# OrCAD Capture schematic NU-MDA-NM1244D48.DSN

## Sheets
1 Connect: size A4; title: Nu-MDA-NM1244D48_Connect; rev: V1.0
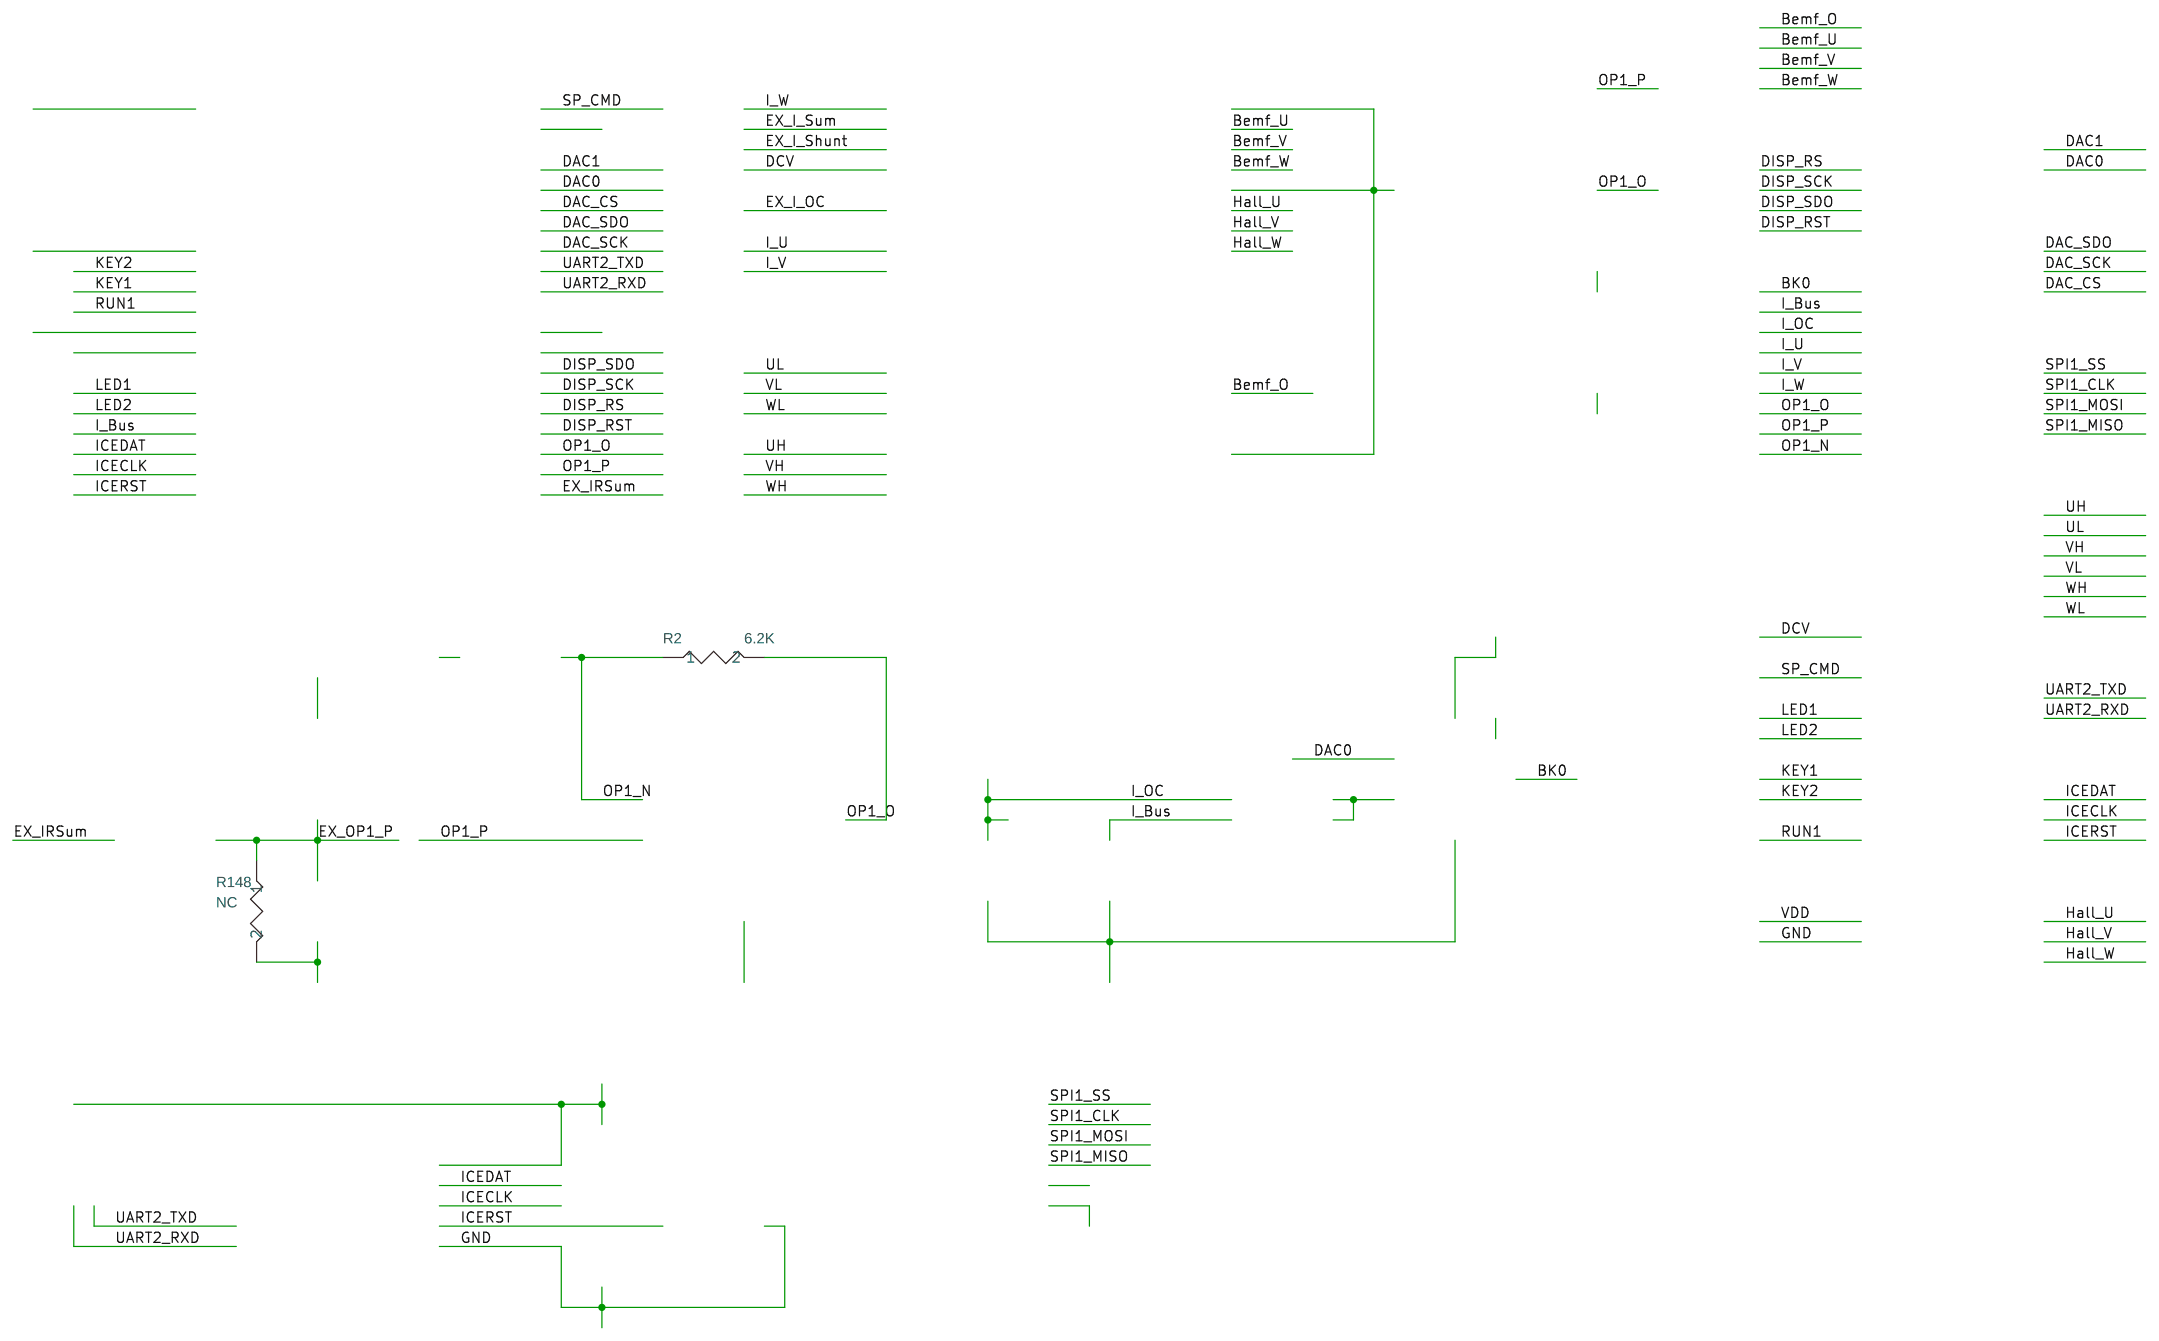
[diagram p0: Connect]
2 NM1244D48: size A3; title: Nu-MDA-NM1244D48
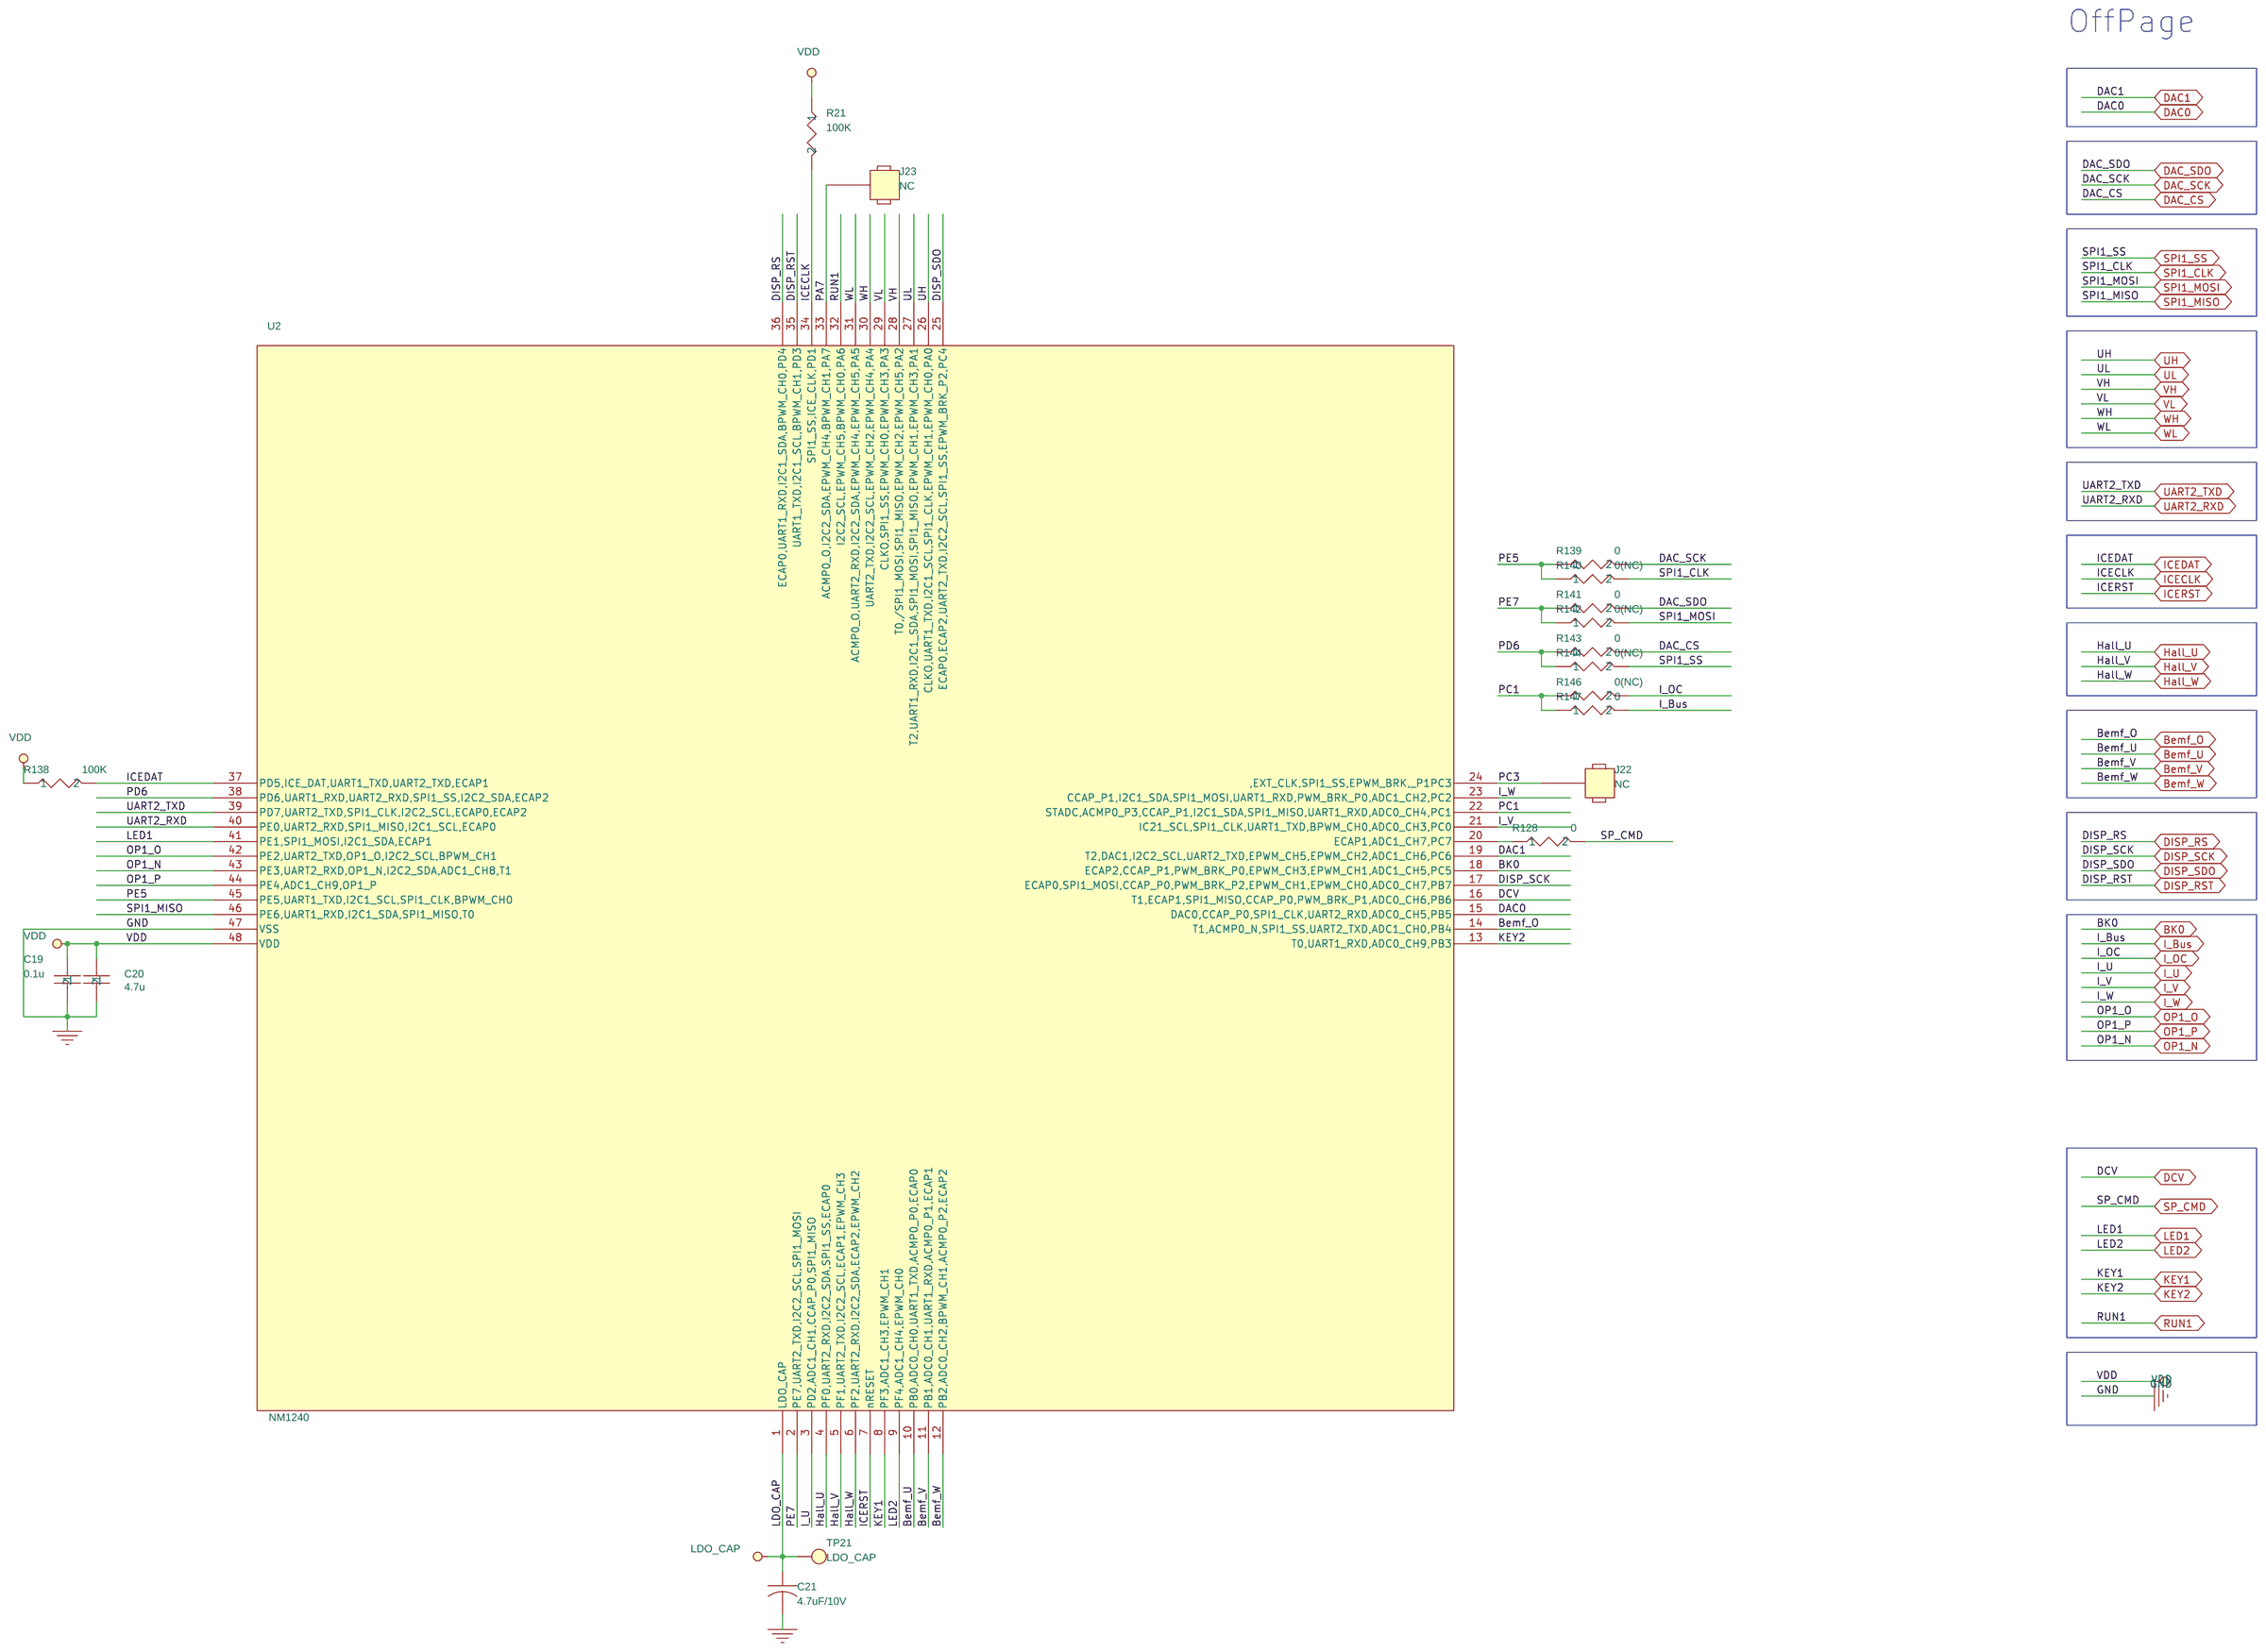
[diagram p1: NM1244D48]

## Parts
sheet Connect
R2  6.2K  [R0603]
R148  NC  [R0603]
sheet NM1244D48
C19  0.1u  [C0603]
C20  4.7u  [C0603]
C21  4.7uF/10V  [TANT-A]
J22  NC  [sip-1p]
J23  NC  [sip-1p]
R21  100K  [R0603]
R128  0  [R0603]
R138  100K  [R0603]
R139  0  [R0603]
R140  0(NC)  [R0603]
R141  0  [R0603]
R142  0(NC)  [R0603]
R143  0  [R0603]
R144  0(NC)  [R0603]
R146  0(NC)  [R0603]
R147  0  [R0603]
TP21  LDO_CAP  [TEST_POINT_2MM_SMD]
U2  NM1240  [LQFP-48]

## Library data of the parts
R2 R128 = R_1K
R148 = R_10K
C19 = C_0.1u
C20 = C_1u
C21 = C_1uF_16V
J22 J23 = HEADER_1
R21 = R_100K_1
R138 = R_100K
R139 = R_1K_6
R140 = R_1K_2
R141 = R_1K_7
R142 = R_1K_8
R143 = R_1K_1
R144 = R_1K_4
R146 = R_1K_3
R147 = R_1K_5
TP21 = T_POINT_R
U2 = TF5103_3

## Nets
GND: C19.2 C20.2 C21.2 U2.47(VSS)
VDD: C19.1 C20.1 R21.1 R138.1 U2.48(VDD)
Bemf_O: U2.14(T1,ACMP0_N,SPI1_SS,UART2_TXD,ADC1_CH0,PB4)
Bemf_U: U2.10(PB0,ADC0_CH0,UART1_TXD,ACMP0_P0,ECAP0)
Bemf_V: U2.11(PB1,ADC0_CH1,UART1_RXD,ACMP0_P1,ECAP1)
Bemf_W: U2.12(PB2,ADC0_CH2,BPWM_CH1,ACMP0_P2,ECAP2)
BK0: U2.18(ECAP2,CCAP_P1,PWM_BRK_P0,EPWM_CH3,EPWM_CH1,ADC1_CH5,PC5)
DAC0: U2.15(DAC0,CCAP_P0,SPI1_CLK,UART2_RXD,ADC0_CH5,PB5)
DAC1: U2.19(T2,DAC1,I2C2_SCL,UART2_TXD,EPWM_CH5,EPWM_CH2,ADC1_CH6,PC6)
DAC_CS: R143.2
DAC_SCK: R139.2
DAC_SDO: R141.2
DCV: U2.16(T1,ECAP1,SPI1_MISO,CCAP_P0,PWM_BRK_P1,ADC0_CH6,PB6)
DISP_RS: U2.36(ECAP0,UART1_RXD,I2C1_SDA,BPWM_CH0,PD4)
DISP_RST: U2.35(UART1_TXD,I2C1_SCL,BPWM_CH1,PD3)
DISP_SCK: U2.17(ECAP0,SPI1_MOSI,CCAP_P0,PWM_BRK_P2,EPWM_CH1,EPWM_CH0,ADC0_CH7,PB7)
DISP_SDO: U2.25(ECAP0,ECAP2,UART2_TXD,I2C2_SCL,SPI1_SS,EPWM_BRK_P2,PC4)
EX_OP1_P: R148.1
Hall_U: U2.4(PF0,UART2_RXD,I2C2_SDA,SPI1_SS,ECAP0)
Hall_V: U2.5(PF1,UART2_TXD,I2C2_SCL,ECAP1,EPWM_CH3)
Hall_W: U2.6(PF2,UART2_RXD,I2C2_SDA,ECAP2,EPWM_CH2)
I_Bus: R147.2
I_OC: R146.2
I_U: U2.3(PD2,ADC1_CH1,CCAP_P0,SPI1_MISO)
I_V: U2.21(IC21_SCL,SPI1_CLK,UART1_TXD,BPWM_CH0,ADC0_CH3,PC0)
I_W: U2.23(CCAP_P1,I2C1_SDA,SPI1_MOSI,UART1_RXD,PWM_BRK_P0,ADC1_CH2,PC2)
ICECLK: R21.2 U2.34(SPI1_SS,ICE_CLK,PD1)
ICEDAT: R138.2 U2.37(PD5,ICE_DAT,UART1_TXD,UART2_TXD,ECAP1)
ICERST: U2.7(nRESET)
KEY1: U2.8(PF3,ADC1_CH3,EPWM_CH1)
KEY2: U2.13(T0,UART1_RXD,ADC0_CH9,PB3)
LDO_CAP: C21.1 TP21.1(TP) U2.1(LDO_CAP)
LED1: U2.41(PE1,SPI1_MOSI,I2C1_SDA,ECAP1)
LED2: U2.9(PF4,ADC1_CH4,EPWM_CH0)
OP1_N: R2.1
OP1_N (page NM1244D48): U2.43(PE3,UART2_RXD,OP1_N,I2C2_SDA,ADC1_CH8,T1)
OP1_O: R2.2
OP1_O (page NM1244D48): U2.42(PE2,UART2_TXD,OP1_O,I2C2_SCL,BPWM_CH1)
OP1_P: U2.44(PE4,ADC1_CH9,OP1_P)
PA7: J23.1 U2.33(ACMP0_O,I2C2_SDA,EPWM_CH4,BPWM_CH1,PA7)
PC1: R146.1 R147.1 U2.22(STADC,ACMP0_P3,CCAP_P1,I2C1_SDA,SPI1_MISO,UART1_RXD,ADC0_CH4,PC1)
PC3: J22.1 U2.24(,EXT_CLK,SPI1_SS,EPWM_BRK,_P1PC3)
PD6: R143.1 R144.1 U2.38(PD6,UART1_RXD,UART2_RXD,SPI1_SS,I2C2_SDA,ECAP2)
PE5: R139.1 R140.1 U2.45(PE5,UART1_TXD,I2C1_SCL,SPI1_CLK,BPWM_CH0)
PE7: R141.1 R142.1 U2.2(PE7,UART2_TXD,I2C2_SCL,SPI1_MOSI)
RUN1: U2.32(I2C2_SCL,EPWM_CH5,BPWM_CH0,PA6)
SP_CMD: R128.2
SPI1_CLK: R140.2
SPI1_MISO: U2.46(PE6,UART1_RXD,I2C1_SDA,SPI1_MISO,T0)
SPI1_MOSI: R142.2
SPI1_SS: R144.2
UART2_RXD: U2.40(PE0,UART2_RXD,SPI1_MISO,I2C1_SCL,ECAP0)
UART2_TXD: U2.39(PD7,UART2_TXD,SPI1_CLK,I2C2_SCL,ECAP0,ECAP2)
UH: U2.26(CLKO,UART1_TXD,I2C1_SCL,SPI1_CLK,EPWM_CH1,EPWM_CH0,PA0)
UL: U2.27(T2,UART1_RXD,I2C1_SDA,SPI1_MOSI,SPI1_MISO,EPWM_CH1,EPWM_CH3,PA1)
VH: U2.28(T0,/SPI1_MOSI,SPI1_MISO,EPWM_CH2,EPWM_CH5,PA2)
VL: U2.29(CLKO,SPI1_SS,EPWM_CH0,EPWM_CH3,PA3)
WH: U2.30(UART2_TXD,I2C2_SCL,EPWM_CH2,EPWM_CH4,PA4)
WL: U2.31(ACMP0_O,UART2_RXD,I2C2_SDA,EPWM_CH4,EPWM_CH5,PA5)
N234237: R128.1 U2.20(ECAP1,ADC1_CH7,PC7)

Not connected (* = marked no-connect by the designer): R148 2

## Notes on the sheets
sheet 2
- OffPage
